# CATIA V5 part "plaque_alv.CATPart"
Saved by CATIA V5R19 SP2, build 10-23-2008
Part number: plaque_alv
Bounding box of the stored display mesh (mm): x -50.64 to 50.64, y -183 to 183, z 0 to 4
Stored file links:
  C:\Users\Utilisateur\Desktop\Mes dossiers\Centrale Lyon\EPSA\Batterie\conception\Modèle Catia\Avec 5 colonnes\Plaque alvéolée c5\plaque_alv.CATPart
  C:\Users\Utilisateur\Desktop\Mes dossiers\Centrale Lyon\EPSA\Batterie\conception\Modèle Catia\Avec 5 colonnes\Plaque alvéolée c5\plaque_alveolee_c5_V1.CATProduct
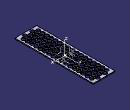
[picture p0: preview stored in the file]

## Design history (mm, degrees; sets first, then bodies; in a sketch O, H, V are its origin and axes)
AxisSystem1: origin (0, 0, 0), X (1, 0, 0), Y (0, 1, 0), Z (0, 0, 1)
Set1
  Sketch1 on XY plane of AxisSystem1, origin (0, 0, 0), H (1, 0, 0), V (0, 1, 0)
    line L1 (-50.64, 183) -> (50.64, 183)
    line L2 (50.64, 183) -> (50.64, -183)
    line L3 (50.64, -183) -> (-50.64, -183)
    line L4 (-50.64, -183) -> (-50.64, 183)
    reference projected point E1 (0, 0) from Point1
    reference projected point E2 (0, 0) from Point1
    reference projected point E3 (0, 0) from Point1
    reference projected point E4 (0, 0) from Point1
    distance E1 L2 = 50.64
    distance E2 L4 = 50.64
    distance E3 L3 = 183
    distance E4 L1 = 183
    horizontal: L1 H, L3 H
    vertical: L2 V, L4 V
Set2
  Point1 to Point3: linked copy from another document
  Point4 "Point.4": linked copy from another document
  Point5 "Point.5": linked copy from another document
Body1 (main body)
  Pad1: profile Sketch1, direction (0, 0, 1), length 4
  Sketch2 on end face of Pad1, origin (0, 0, 4), H (1, 0, 0), V (0, 1, 0)
    circle A1 centre (0, 0) radius 9
    reference projected point E1 (0, 0) from Point1
    reference projected point E2 (0, 0) from Point1
    radius A1 = 9
    concentricity: A1 E1, E2 A1
  Sketch3 on end face of Pad1, origin (0, 0, 4), H (1, 0, 0), V (0, 1, 0)
    circle A1 centre (17.32, 10) radius 9
    reference projected point E1 (17.32, 10) from Point2
    construction line L1 (-5.6857, 7.1096) -> (12.8199, 17.7942)
    point P2 (12.8199, 17.7942)
    reference projected circle E2 centre (0, 0) radius 9 from Sketch2.A1
    construction line L2 (21.8201, 2.2058) -> (4.3829, -7.8618)
    point P4 (21.8201, 2.2058)
    reference projected circle E3 centre (0, 0) radius 9 from Sketch2.A1
    concentricity: A1 E1
    coincidence: P2 A1, P4 A1
    tangency: L1 A1, L1 E2, L2 A1, E3 L2
    parallelism: L1 L2
  Sketch4 on end face of Pad1, origin (0, 0, 4), H (1, 0, 0), V (0, 1, 0)
    circle A1 centre (34.64, 0) radius 9
    point P1 (34.64, 0)
    reference projected point E1 (34.64, 0) from Point3
    construction line L1 (18.7425, 19.5711) -> (39.1401, 7.7942)
    point P2 (39.1401, 7.7942)
    reference projected circle E2 centre (17.32, 10) radius 9 from Sketch3.A1
    construction line L2 (30.1399, -7.7942) -> (11.3467, 3.0564)
    point P4 (30.1399, -7.7942)
    reference projected circle E3 centre (17.32, 10) radius 9 from Sketch3.A1
    coincidence: P1 H, P2 A1, P4 A1
    concentricity: A1 E1
    tangency: L1 A1, E2 L1, L2 E3, A1 L2
    parallelism: L2 L1
  Pocket1 "trou1": profile Sketch2, direction (0, 0, -1), length 4
  Pocket2 "trou2": profile Sketch3, direction (0, 0, -1), length 4
  Pocket3 "trou3": profile Sketch4, direction (0, 0, -1), length 4
  RectPattern1: of Pocket1, direction 1 instances 9, spacing 20, along YZ plane of AxisSystem1
  RectPattern2: of Pocket1, direction 1 instances 9, spacing 20, along YZ plane of AxisSystem1 reversed
  RectPattern3: of Pocket2, direction 1 instances 9, spacing 20, along YZ plane of AxisSystem1
  RectPattern4: of Pocket2, direction 1 instances 10, spacing 20, along YZ plane of AxisSystem1 reversed
  RectPattern5: of Pocket3, direction 1 instances 9, spacing 20, along YZ plane of AxisSystem1
  RectPattern6: of Pocket3, direction 1 instances 9, spacing 20, along YZ plane of AxisSystem1 reversed
  Sketch5 "trou4" on end face of Pad1, origin (0, 0, 4), H (1, 0, 0), V (0, 1, 0)
    circle A1 centre (-17.32, 10) radius 9
    point P1 (-17.32, 10)
    reference projected point E1 (-17.32, 10) from Point4
    construction line L1 (3.4162, 8.42) -> (-12.8199, 17.7942)
    point P2 (-12.8199, 17.7942)
    reference projected circle E2 centre (0, 0) radius 9 from edge [end face of Pad1 | face of Pocket1 from Sketch2.A1]
    construction line L2 (-0.8515, -9.9007) -> (-21.8201, 2.2058)
    point P4 (-21.8201, 2.2058)
    reference projected circle E3 centre (0, 0) radius 9 from edge [end face of Pad1 | face of Pocket1 from Sketch2.A1]
    coincidence: P1 E1, P2 A1, P4 A1
    tangency: L1 A1, E2 L1, L2 A1, E3 L2
    parallelism: L1 L2
  Sketch6 "trou5" on end face of Pad1, origin (0, 0, 4), H (1, 0, 0), V (0, 1, 0)
    circle A1 centre (-34.642, 0) radius 9
    point P1 (-34.642, 0)
    reference projected point E1 (-34.642, 0) from Point5
    construction line L1 (-39.1417, 7.7944) -> (-21.2615, 18.1167)
    point P2 (-39.1417, 7.7944)
    reference projected circle E2 centre (-17.32, 10) radius 9 from Sketch5.A1
    construction line L2 (-17.0291, -0.2241) -> (-30.1423, -7.7944)
    point P4 (-30.1423, -7.7944)
    reference projected circle E3 centre (-17.32, 10) radius 9 from Sketch5.A1
    coincidence: P1 H, P2 A1, P4 A1
    concentricity: A1 E1
    tangency: L1 A1, L1 E2, L2 E3, A1 L2
    parallelism: L1 L2
  Pocket4 "trou4": profile Sketch5, direction (0, 0, -1), length 4
  Pocket5 "trou5": profile Sketch6, direction (0, 0, -1), length 4
  RectPattern7: of Pocket4, direction 1 instances 9, spacing 20, along YZ plane of AxisSystem1
  RectPattern8: of Pocket4, direction 1 instances 10, spacing 20, along edge [YZ plane of AxisSystem1 | XY plane of AxisSystem1] reversed
  RectPattern9: of Pocket5, direction 1 instances 9, spacing 20, along YZ plane of AxisSystem1
  RectPattern10: of Pocket5, direction 1 instances 9, spacing 20, along YZ plane of AxisSystem1 reversed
